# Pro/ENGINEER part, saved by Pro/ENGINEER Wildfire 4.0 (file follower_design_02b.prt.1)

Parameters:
  METRIC = "NO"

Other parameters: PITCH, DRILL_DIAMETER, THREAD_DIAMETER, THREADS_PER_INCH, THREAD_DEPTH, THREAD_LENGTH, DRILL_POINT_ANGLE, DRILL_DEPTH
